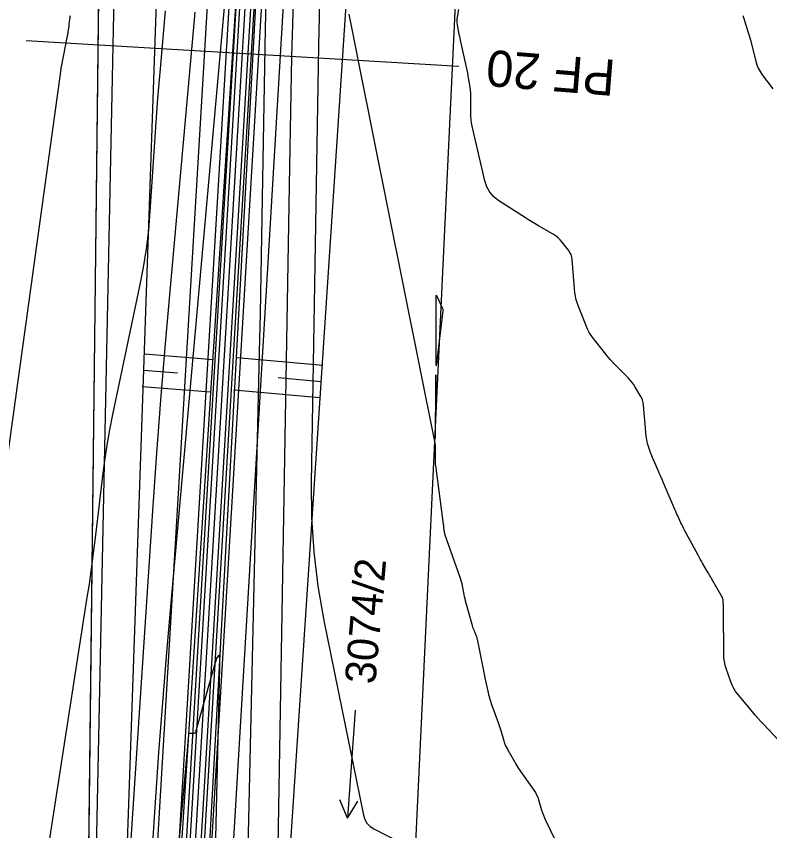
# Model space of a CAD drawing. Extents: x -534410 to -534262, y -1190162 to -1189584.
# Drawn here: x -534369.58 to -534348.73, y -1189677.27 to -1189654.72 of the extents above; entities that cross this region are included whole.
import ezdxf

# ---------------------------------------------------------------- set-up
doc = ezdxf.new("R2010")
doc.units = 0
for name, color, linetype in [('30', 7, 'Continuous'), ('31', 7, 'Continuous'), ('_linie', 7, 'Continuous'), ('_N_osa', 7, 'Continuous'), ('_N_tenká', 7, 'Continuous'), ('_N_tenká_velmi', 7, 'Continuous'), ('_N_text', 7, 'Continuous'), ('_tenka', 7, 'Continuous'), ('_velmi_tenka', 7, 'Continuous'), ('Default', 7, 'Continuous'), ('Hranice parcel', 7, 'Continuous'), ('Parcelní čísla', 7, 'Continuous'), ('Značky kultur', 7, 'Continuous')]:
    doc.layers.add(name, color=color, linetype=linetype)

msp = doc.modelspace()

# ---------------------------------------------------------------- linework, layer by layer
at = {"layer": '30'}
for points in [[(-534362.459, -1189684.707), (-534362.015, -1189658.872), (-534361.953, -1189655.843), (-534361.869, -1189652.815)], [(-534370.511, -1189671.838), (-534368.346, -1189656.186), (-534368.343, -1189656.163), (-534368.34, -1189656.14), (-534368.339, -1189656.129), (-534368.337, -1189656.117), (-534368.167, -1189655.26), (-534368.161, -1189655.232), (-534368.156, -1189655.205), (-534368.151, -1189655.177), (-534368.147, -1189655.15), (-534368.122, -1189654.995), (-534368.121, -1189654.984), (-534368.12, -1189654.973), (-534368.12, -1189654.95), (-534368.119, -1189654.939), (-534368.118, -1189654.928), (-534368.096, -1189654.761), (-534368.094, -1189654.74), (-534368.091, -1189654.72), (-534368.087, -1189654.7)], [(-534364.64, -1189654.602), (-534364.726, -1189655.531), (-534365.346, -1189662.432), (-534365.472, -1189663.892), (-534365.591, -1189665.352), (-534365.7, -1189666.814), (-534365.801, -1189668.276), (-534366.596, -1189680.297)], [(-534360.376, -1189654.662), (-534360.319, -1189654.986), (-534360, -1189656.556), (-534359.925, -1189656.925), (-534359.851, -1189657.294), (-534359.776, -1189657.664), (-534359.702, -1189658.033), (-534358.003, -1189666.536), (-534357.998, -1189666.566), (-534357.994, -1189666.597), (-534357.991, -1189666.628), (-534357.99, -1189666.659), (-534357.989, -1189666.783), (-534357.989, -1189666.814), (-534357.989, -1189666.845), (-534357.989, -1189666.875), (-534357.989, -1189666.906), (-534357.99, -1189667.03), (-534357.99, -1189667.061), (-534357.988, -1189667.092), (-534357.986, -1189667.122), (-534357.982, -1189667.153), (-534357.765, -1189668.784), (-534357.762, -1189668.806), (-534357.76, -1189668.828), (-534357.757, -1189668.85), (-534357.755, -1189668.873), (-534357.747, -1189668.961), (-534357.744, -1189668.983), (-534357.74, -1189669.005), (-534357.735, -1189669.026), (-534357.728, -1189669.047), (-534357.305, -1189670.251), (-534357.285, -1189670.308), (-534357.269, -1189670.367), (-534357.254, -1189670.426), (-534357.242, -1189670.485), (-534357.197, -1189670.725), (-534357.186, -1189670.784), (-534357.173, -1189670.844), (-534357.158, -1189670.903), (-534357.142, -1189670.962), (-534356.977, -1189671.555), (-534356.965, -1189671.593), (-534356.953, -1189671.632), (-534356.939, -1189671.67), (-534356.924, -1189671.708), (-534356.863, -1189671.859), (-534356.849, -1189671.897), (-534356.837, -1189671.935), (-534356.826, -1189671.974), (-534356.817, -1189672.014), (-534356.69, -1189672.656), (-534356.672, -1189672.75), (-534356.653, -1189672.844), (-534356.633, -1189672.939), (-534356.614, -1189673.033), (-534356.535, -1189673.409), (-534356.514, -1189673.503), (-534356.489, -1189673.595), (-534356.461, -1189673.687), (-534356.429, -1189673.777), (-534356.244, -1189674.273), (-534356.224, -1189674.329), (-534356.205, -1189674.386), (-534356.187, -1189674.443), (-534356.171, -1189674.5), (-534356.093, -1189674.785), (-534356.084, -1189674.814), (-534356.073, -1189674.843), (-534356.061, -1189674.872), (-534356.048, -1189674.899), (-534355.991, -1189675.009), (-534355.977, -1189675.036), (-534355.962, -1189675.064), (-534355.947, -1189675.091), (-534355.932, -1189675.118), (-534355.798, -1189675.358), (-534355.77, -1189675.406), (-534355.741, -1189675.454), (-534355.71, -1189675.501), (-534355.679, -1189675.547), (-534355.256, -1189676.149), (-534355.216, -1189676.212), (-534355.181, -1189676.277), (-534355.152, -1189676.345), (-534355.128, -1189676.415), (-534355.042, -1189676.701), (-534355.019, -1189676.772), (-534354.994, -1189676.842), (-534354.966, -1189676.911), (-534354.935, -1189676.979), (-534354.661, -1189677.55)], [(-534349.473, -1189654.693), (-534349.446, -1189654.782), (-534349.332, -1189655.136), (-534349.304, -1189655.225), (-534349.278, -1189655.314), (-534349.253, -1189655.404), (-534349.23, -1189655.494), (-534349.115, -1189655.96), (-534349.085, -1189656.061), (-534349.046, -1189656.157), (-534348.996, -1189656.249), (-534348.938, -1189656.336), (-534348.644, -1189656.729)], [(-534364.158, -1189681.827), (-534363.949, -1189672.734), (-534363.953, -1189672.49), (-534363.981, -1189672.405), (-534364.033, -1189672.478), (-534364.11, -1189672.71), (-534364.625, -1189674.537), (-534364.633, -1189674.555), (-534364.645, -1189674.568), (-534364.661, -1189674.576), (-534364.681, -1189674.578), (-534364.77, -1189674.577), (-534364.789, -1189674.579), (-534364.804, -1189674.587), (-534364.813, -1189674.6), (-534364.818, -1189674.62), (-534365.429, -1189681.422)]]:
    msp.add_lwpolyline(points, dxfattribs=at)
for points in [[(-534357.766, -1189662.872), (-534357.766, -1189662.867), (-534357.766, -1189662.861), (-534357.766, -1189662.85), (-534357.767, -1189662.845), (-534357.768, -1189662.839), (-534357.776, -1189662.818), (-534357.779, -1189662.809), (-534357.783, -1189662.8), (-534357.926, -1189662.495), (-534357.948, -1189662.456), (-534357.963, -1189662.445), (-534357.972, -1189662.462), (-534357.975, -1189662.506), (-534357.974, -1189664.174), (-534357.971, -1189664.339), (-534357.961, -1189664.395), (-534357.945, -1189664.341), (-534357.922, -1189664.177)], [(-534357.967, -1189665.095), (-534357.967, -1189665.068), (-534357.967, -1189665.04), (-534357.967, -1189665.012), (-534357.968, -1189664.9), (-534357.968, -1189664.872), (-534357.969, -1189664.845), (-534357.969, -1189664.817), (-534357.97, -1189664.789), (-534357.972, -1189664.671), (-534357.973, -1189664.65), (-534357.974, -1189664.643), (-534357.974, -1189664.65), (-534357.974, -1189664.671), (-534357.988, -1189666.214), (-534357.989, -1189666.358), (-534357.989, -1189666.406), (-534357.987, -1189666.358), (-534357.985, -1189666.214), (-534357.967, -1189665.123)]]:
    msp.add_lwpolyline(points, close=True, dxfattribs=at)
at = {"layer": '31'}
for points in [[(-534361.181, -1189653.897), (-534361.215, -1189655.536), (-534361.422, -1189667.638), (-534361.413, -1189668.597), (-534361.351, -1189669.551), (-534361.238, -1189670.5), (-534361.072, -1189671.445), (-534359.975, -1189676.838), (-534359.937, -1189676.959), (-534359.877, -1189677.063), (-534359.793, -1189677.15), (-534359.686, -1189677.219), (-534358.985, -1189677.578)], [(-534366.669, -1189692.065), (-534366.397, -1189686.966), (-534366.337, -1189685.881), (-534366.274, -1189684.796), (-534366.207, -1189683.711), (-534366.137, -1189682.626), (-534365.732, -1189676.49), (-534365.636, -1189675.106), (-534365.532, -1189673.723), (-534365.42, -1189672.34), (-534365.3, -1189670.958), (-534363.781, -1189654.053)], [(-534362.676, -1189654.218), (-534362.693, -1189655.065), (-534362.774, -1189659.756), (-534362.793, -1189660.82), (-534362.813, -1189661.885), (-534362.835, -1189662.949), (-534362.859, -1189664.013), (-534363.288, -1189682.613), (-534363.31, -1189683.924), (-534363.316, -1189685.235), (-534363.304, -1189686.546), (-534363.277, -1189687.857), (-534363.128, -1189693.255)], [(-534368.867, -1189678.859), (-534367.627, -1189670.868), (-534367.562, -1189670.442), (-534367.502, -1189670.014), (-534367.445, -1189669.587), (-534367.392, -1189669.158), (-534367.188, -1189667.444), (-534367.132, -1189667.016), (-534367.067, -1189666.59), (-534366.992, -1189666.165), (-534366.908, -1189665.742), (-534366.16, -1189662.191), (-534366.061, -1189661.677), (-534365.981, -1189661.16), (-534365.919, -1189660.641), (-534365.875, -1189660.119), (-534365.721, -1189657.786), (-534365.693, -1189657.383), (-534365.663, -1189656.981), (-534365.63, -1189656.579), (-534365.595, -1189656.177), (-534365.451, -1189654.569)], [(-534348.496, -1189674.755), (-534348.895, -1189674.33), (-534348.975, -1189674.243), (-534349.054, -1189674.156), (-534349.132, -1189674.067), (-534349.208, -1189673.978), (-534349.616, -1189673.492), (-534349.675, -1189673.414), (-534349.727, -1189673.331), (-534349.771, -1189673.244), (-534349.807, -1189673.152), (-534349.935, -1189672.777), (-534349.963, -1189672.682), (-534349.983, -1189672.586), (-534349.996, -1189672.489), (-534350, -1189672.39), (-534350.009, -1189671.178), (-534350.01, -1189671.145), (-534350.01, -1189671.111), (-534350.011, -1189671.078), (-534350.012, -1189671.045), (-534350.017, -1189670.911), (-534350.02, -1189670.878), (-534350.027, -1189670.847), (-534350.038, -1189670.816), (-534350.053, -1189670.787), (-534350.328, -1189670.307), (-534350.36, -1189670.252), (-534350.392, -1189670.196), (-534350.424, -1189670.141), (-534350.457, -1189670.085), (-534350.587, -1189669.864), (-534350.619, -1189669.808), (-534350.651, -1189669.753), (-534350.682, -1189669.696), (-534350.712, -1189669.64), (-534351.085, -1189668.945), (-534351.112, -1189668.894), (-534351.138, -1189668.844), (-534351.163, -1189668.793), (-534351.187, -1189668.741), (-534351.283, -1189668.535), (-534351.307, -1189668.484), (-534351.33, -1189668.432), (-534351.353, -1189668.38), (-534351.376, -1189668.328), (-534351.677, -1189667.621), (-534351.71, -1189667.543), (-534351.744, -1189667.465), (-534351.777, -1189667.387), (-534351.812, -1189667.31), (-534351.975, -1189666.94), (-534351.995, -1189666.892), (-534352.014, -1189666.843), (-534352.032, -1189666.795), (-534352.048, -1189666.745), (-534352.11, -1189666.546), (-534352.124, -1189666.496), (-534352.135, -1189666.446), (-534352.144, -1189666.395), (-534352.15, -1189666.343), (-534352.224, -1189665.482), (-534352.234, -1189665.411), (-534352.252, -1189665.343), (-534352.278, -1189665.277), (-534352.312, -1189665.214), (-534352.464, -1189664.968), (-534352.503, -1189664.907), (-534352.546, -1189664.85), (-534352.592, -1189664.794), (-534352.642, -1189664.742), (-534352.988, -1189664.39), (-534353.062, -1189664.314), (-534353.133, -1189664.235), (-534353.202, -1189664.154), (-534353.269, -1189664.072), (-534353.64, -1189663.597), (-534353.689, -1189663.529), (-534353.733, -1189663.459), (-534353.771, -1189663.386), (-534353.804, -1189663.31), (-534353.952, -1189662.936), (-534353.97, -1189662.89), (-534353.987, -1189662.844), (-534354.004, -1189662.798), (-534354.02, -1189662.752), (-534354.083, -1189662.566), (-534354.098, -1189662.519), (-534354.109, -1189662.472), (-534354.117, -1189662.424), (-534354.123, -1189662.375), (-534354.197, -1189661.457), (-534354.208, -1189661.385), (-534354.228, -1189661.318), (-534354.259, -1189661.254), (-534354.299, -1189661.194), (-534354.481, -1189660.961), (-534354.529, -1189660.905), (-534354.581, -1189660.855), (-534354.638, -1189660.81), (-534354.699, -1189660.77), (-534355.127, -1189660.521), (-534355.219, -1189660.467), (-534355.311, -1189660.411), (-534355.402, -1189660.355), (-534355.492, -1189660.298), (-534356.224, -1189659.826), (-534356.363, -1189659.718), (-534356.473, -1189659.591), (-534356.556, -1189659.444), (-534356.611, -1189659.278), (-534356.965, -1189657.76), (-534356.983, -1189657.67), (-534356.995, -1189657.58), (-534357.002, -1189657.489), (-534357.004, -1189657.397), (-534356.998, -1189657.007), (-534356.998, -1189656.926), (-534357.002, -1189656.845), (-534357.01, -1189656.765), (-534357.022, -1189656.684), (-534357.076, -1189656.364), (-534357.09, -1189656.284), (-534357.105, -1189656.205), (-534357.121, -1189656.125), (-534357.138, -1189656.046), (-534357.288, -1189655.382), (-534357.3, -1189655.328), (-534357.311, -1189655.275), (-534357.322, -1189655.221), (-534357.332, -1189655.167), (-534357.373, -1189654.951), (-534357.38, -1189654.898), (-534357.383, -1189654.844), (-534357.381, -1189654.791), (-534357.374, -1189654.738), (-534357.336, -1189654.525)]]:
    msp.add_lwpolyline(points, dxfattribs=at)
at = {"layer": '_linie'}
for points in [[(-534366.12, -1189620.81), (-534364.52, -1189627.2), (-534365.69, -1189653.8), (-534366.76, -1189684.81), (-534368.14, -1189748.73), (-534368.38, -1189779.14), (-534368.65, -1189820.64), (-534368.59, -1189847.58), (-534367.2, -1189913.8)], [(-534363.12, -1189621.02), (-534362.79, -1189621.58), (-534361.82, -1189627.79), (-534363.46, -1189653.55), (-534365.47, -1189684.77), (-534366.65, -1189748.83), (-534366.75, -1189779.47), (-534366.9, -1189820.47), (-534366.95, -1189846.72), (-534366.338, -1189888.804), (-534363.85, -1189911.95), (-534357.07, -1189929.19), (-534352.334, -1189940.856)], [(-534359.03, -1189621.26), (-534359.41, -1189621.83), (-534360.84, -1189627.76), (-534362.92, -1189653.56), (-534364.64, -1189685), (-534365.94, -1189748.9), (-534366.02, -1189779.52), (-534366.03, -1189820.5), (-534366.48, -1189846.73), (-534365.511, -1189888.873), (-534362.72, -1189912.12), (-534356.62, -1189928.64), (-534351.589, -1189940.594)]]:
    msp.add_lwpolyline(points, dxfattribs=at)
at = {"layer": '_N_osa'}
msp.add_lwpolyline([(-534351.95, -1189940.722), (-534356.845, -1189928.915), (-534363.285, -1189912.035), (-534365.925, -1189888.838), (-534366.715, -1189846.725), (-534366.465, -1189820.485), (-534366.385, -1189779.495), (-534366.295, -1189748.865), (-534365.055, -1189684.885), (-534363.19, -1189653.555), (-534361.333, -1189627.822)], dxfattribs=at)
at = {"layer": '_N_tenká'}
for points in [[(-534352.92, -1189941.124), (-534357.821, -1189929.303), (-534364.313, -1189912.285), (-534366.973, -1189888.908), (-534367.765, -1189846.73), (-534367.515, -1189820.479), (-534367.435, -1189779.492), (-534367.345, -1189748.853), (-534366.104, -1189684.844), (-534364.238, -1189653.486), (-534362.424, -1189628.352), (-534361.782, -1189627.792)], [(-534350.98, -1189940.319), (-534355.869, -1189928.527), (-534362.257, -1189911.785), (-534364.876, -1189888.769), (-534365.665, -1189846.72), (-534365.415, -1189820.491), (-534365.335, -1189779.498), (-534365.245, -1189748.877), (-534364.006, -1189684.926), (-534362.142, -1189653.624), (-534360.329, -1189628.488), (-534360.884, -1189627.851)]]:
    msp.add_lwpolyline(points, dxfattribs=at)
at = {"layer": '_N_tenká_velmi'}
for points in [[(-534352.366, -1189940.894), (-534357.263, -1189929.081), (-534363.726, -1189912.142), (-534366.374, -1189888.868), (-534367.165, -1189846.727), (-534366.915, -1189820.482), (-534366.835, -1189779.494), (-534366.745, -1189748.86), (-534365.505, -1189684.867), (-534363.639, -1189653.525), (-534361.782, -1189627.792)], [(-534352.181, -1189940.817), (-534357.077, -1189929.007), (-534363.53, -1189912.095), (-534366.174, -1189888.855), (-534366.965, -1189846.726), (-534366.715, -1189820.484), (-534366.635, -1189779.494), (-534366.545, -1189748.862), (-534365.305, -1189684.875), (-534363.439, -1189653.539), (-534361.583, -1189627.805)], [(-534352.089, -1189940.779), (-534356.984, -1189928.97), (-534363.432, -1189912.071), (-534366.074, -1189888.848), (-534366.865, -1189846.726), (-534366.615, -1189820.484), (-534366.535, -1189779.495), (-534366.445, -1189748.863), (-534365.205, -1189684.879), (-534363.34, -1189653.545), (-534361.483, -1189627.812)], [(-534351.812, -1189940.664), (-534356.706, -1189928.86), (-534363.138, -1189911.999), (-534365.775, -1189888.828), (-534366.565, -1189846.724), (-534366.315, -1189820.486), (-534366.235, -1189779.495), (-534366.145, -1189748.867), (-534364.905, -1189684.891), (-534363.04, -1189653.565), (-534361.184, -1189627.831)], [(-534351.719, -1189940.626), (-534356.613, -1189928.823), (-534363.04, -1189911.975), (-534365.675, -1189888.822), (-534366.465, -1189846.724), (-534366.215, -1189820.486), (-534366.135, -1189779.496), (-534366.045, -1189748.868), (-534364.805, -1189684.895), (-534362.941, -1189653.571), (-534361.084, -1189627.838)], [(-534351.534, -1189940.549), (-534356.427, -1189928.749), (-534362.844, -1189911.928), (-534365.475, -1189888.808), (-534366.265, -1189846.723), (-534366.015, -1189820.488), (-534365.935, -1189779.496), (-534365.845, -1189748.87), (-534364.605, -1189684.903), (-534362.741, -1189653.585), (-534360.884, -1189627.851)]]:
    msp.add_lwpolyline(points, dxfattribs=at)
at = {"layer": '_N_text'}
msp.add_lwpolyline([(-534357.331, -1189656.108), (-534369.31, -1189655.395)], dxfattribs=at)
at = {"layer": '_tenka'}
for points in [[(-534349.13, -1189939.73), (-534354.63, -1189926.96), (-534362.03, -1189907.65), (-534364.521, -1189888.74), (-534364.47, -1189846.64), (-534364.29, -1189820.63), (-534364.22, -1189780.69), (-534363.18, -1189749.38), (-534362.5, -1189685.39), (-534360.27, -1189651.6), (-534357.03, -1189627.34), (-534354.77, -1189620.37)], [(-534366.12, -1189620.81), (-534364.52, -1189627.2), (-534365.69, -1189653.8), (-534366.76, -1189684.81), (-534368.14, -1189748.73), (-534368.38, -1189779.14), (-534368.65, -1189820.64), (-534368.59, -1189847.58), (-534367.2, -1189913.8)], [(-534366.12, -1189620.81), (-534364.52, -1189627.2), (-534365.69, -1189653.8), (-534366.76, -1189684.81), (-534368.14, -1189748.73), (-534368.38, -1189779.14), (-534368.65, -1189820.64), (-534368.59, -1189847.58), (-534367.2, -1189913.8)], [(-534363.12, -1189621.02), (-534362.79, -1189621.58), (-534361.82, -1189627.79), (-534363.46, -1189653.55), (-534365.47, -1189684.77), (-534366.65, -1189748.83), (-534366.75, -1189779.47), (-534366.9, -1189820.47), (-534366.95, -1189846.72), (-534366.338, -1189888.804), (-534363.85, -1189911.95), (-534357.07, -1189929.19), (-534352.334, -1189940.856)], [(-534363.12, -1189621.02), (-534362.79, -1189621.58), (-534361.82, -1189627.79), (-534363.46, -1189653.55), (-534365.47, -1189684.77), (-534366.65, -1189748.83), (-534366.75, -1189779.47), (-534366.9, -1189820.47), (-534366.95, -1189846.72), (-534366.338, -1189888.804), (-534363.85, -1189911.95), (-534357.07, -1189929.19), (-534352.334, -1189940.856)], [(-534359.03, -1189621.26), (-534359.41, -1189621.83), (-534360.84, -1189627.76), (-534362.92, -1189653.56), (-534364.64, -1189685), (-534365.94, -1189748.9), (-534366.02, -1189779.52), (-534366.03, -1189820.5), (-534366.48, -1189846.73), (-534365.511, -1189888.873), (-534362.72, -1189912.12), (-534356.62, -1189928.64), (-534351.589, -1189940.594)], [(-534359.03, -1189621.26), (-534359.41, -1189621.83), (-534360.84, -1189627.76), (-534362.92, -1189653.56), (-534364.64, -1189685), (-534365.94, -1189748.9), (-534366.02, -1189779.52), (-534366.03, -1189820.5), (-534366.48, -1189846.73), (-534365.511, -1189888.873), (-534362.72, -1189912.12), (-534356.62, -1189928.64), (-534351.589, -1189940.594)], [(-534368.65, -1189626.81), (-534368.65, -1189626.81), (-534367.31, -1189654.04), (-534367.67, -1189685.23), (-534369.56, -1189748.93), (-534369.48, -1189778.6), (-534369.45, -1189820.62), (-534369.45, -1189847.87), (-534371.206, -1189896.071), (-534372.39, -1189914.47)]]:
    msp.add_lwpolyline(points, dxfattribs=at)
at = {"layer": '_velmi_tenka'}
for p, q in [((-534366.023, -1189664.069), (-534364.139, -1189664.224)), ((-534361.103, -1189664.388), (-534363.484, -1189664.171)), ((-534366.06, -1189664.517), (-534365.118, -1189664.595)), ((-534361.144, -1189664.836), (-534362.334, -1189664.728)), ((-534366.097, -1189664.965), (-534364.213, -1189665.121)), ((-534361.184, -1189665.284), (-534363.566, -1189665.067))]:
    msp.add_line(p, q, dxfattribs=at)
at = {"layer": 'Default'}
msp.add_line((-534367.31, -1189654.04), (-534367.67, -1189685.23), dxfattribs=at)
msp.add_lwpolyline([(-534349.13, -1189939.73), (-534354.63, -1189926.96), (-534362.03, -1189907.65), (-534364.521, -1189888.74), (-534364.47, -1189846.64), (-534364.29, -1189820.63), (-534364.22, -1189780.69), (-534363.18, -1189749.38), (-534362.5, -1189685.39), (-534360.27, -1189651.6), (-534357.03, -1189627.34), (-534354.77, -1189620.37)], dxfattribs=at)
at = {"layer": 'Hranice parcel'}
for p, q in [((-534359.48, -1189697.97), (-534356.61, -1189636.93)), ((-534366.56, -1189638.19), (-534367.77, -1189697.34))]:
    msp.add_line(p, q, dxfattribs=at)
at = {"layer": 'Značky kultur'}
for p, q in [((-534360.207, -1189673.932), (-534360.417, -1189676.924)), ((-534360.417, -1189676.924), (-534360.633, -1189676.419)), ((-534360.417, -1189676.924), (-534360.133, -1189676.454))]:
    msp.add_line(p, q, dxfattribs=at)

# ---------------------------------------------------------------- texts
at = {"layer": '_N_text'}
msp.add_text('PF 20', height=1, rotation=175.4144, dxfattribs=at).set_placement((-534352.97, -1189655.929))
at = {"layer": 'Parcelní čísla'}
msp.add_text('3074/2', height=0.85, rotation=85, dxfattribs=at).set_placement((-534359.647, -1189673.232))

doc.saveas('drawing.dxf')
